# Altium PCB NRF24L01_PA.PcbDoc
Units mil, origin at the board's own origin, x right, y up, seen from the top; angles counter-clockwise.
Board outline 865.03 x 605.03 mil, 4 copper layers (Top Layer, Internal Plane 1, Signal Layer 1, Bottom Layer), stack 29.965 mil thick; 31 components, 23 nets, 111 pads, 55 vias.
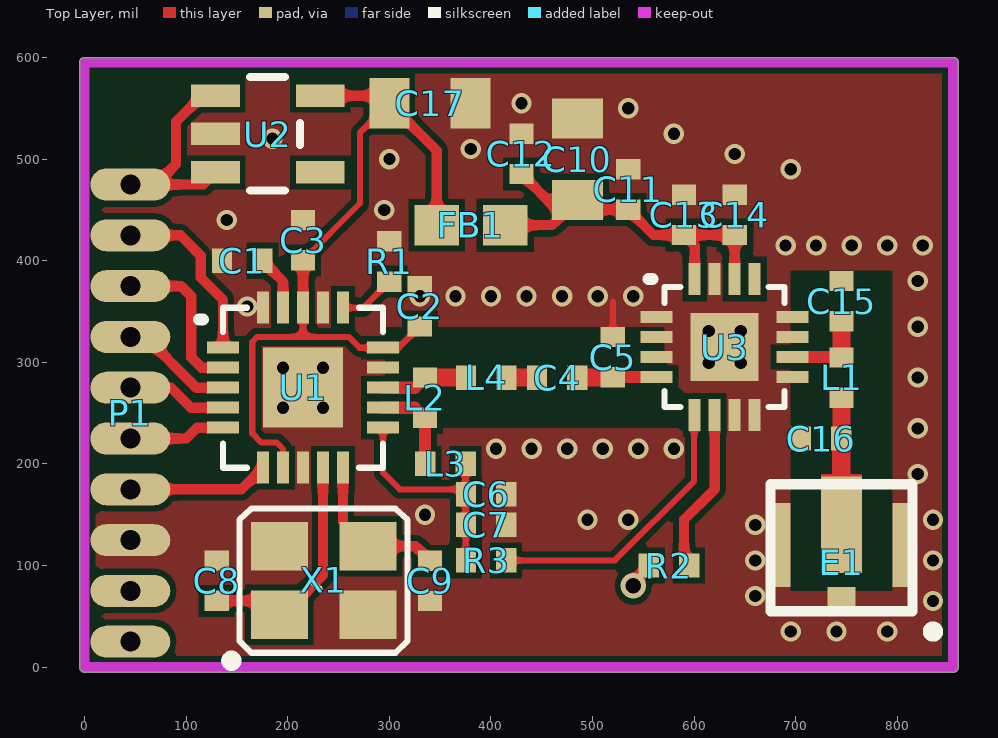
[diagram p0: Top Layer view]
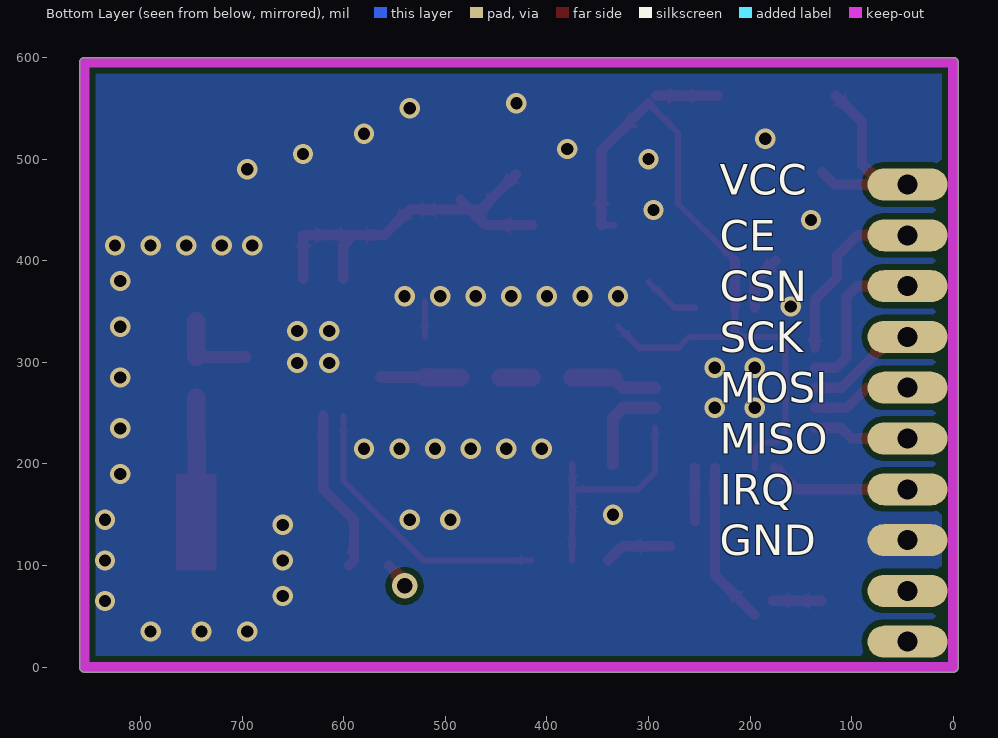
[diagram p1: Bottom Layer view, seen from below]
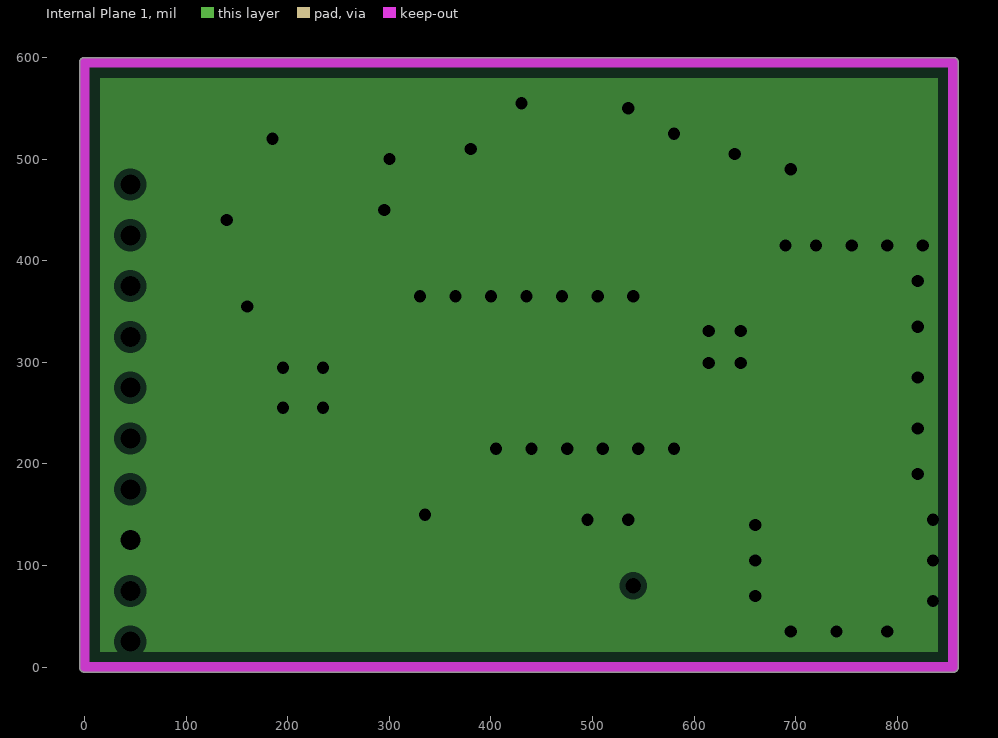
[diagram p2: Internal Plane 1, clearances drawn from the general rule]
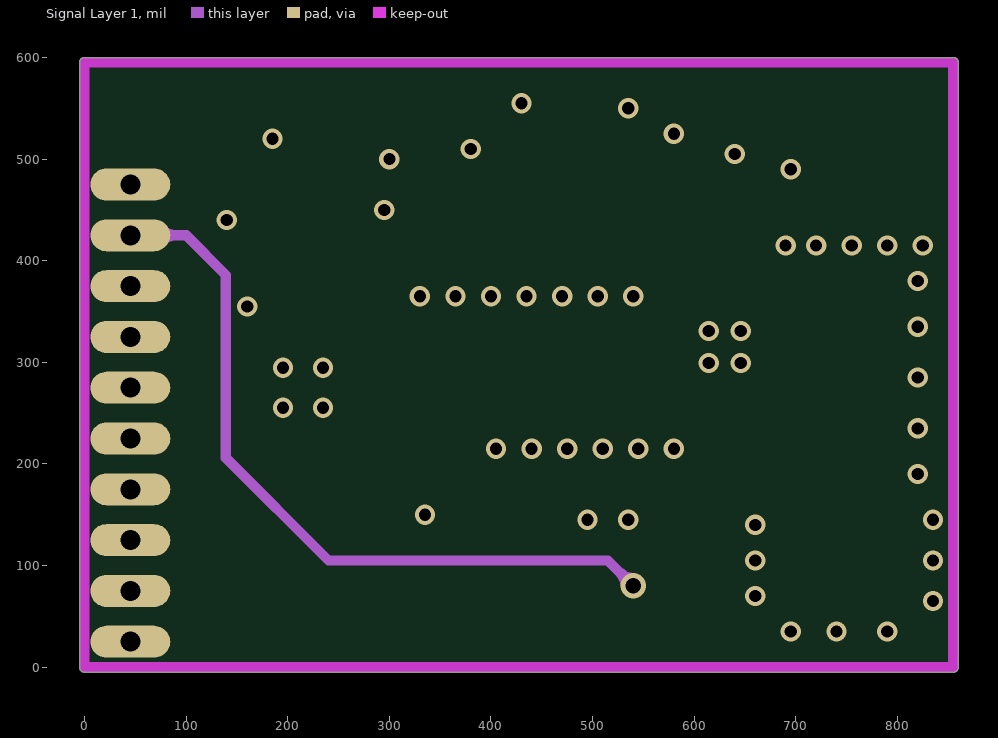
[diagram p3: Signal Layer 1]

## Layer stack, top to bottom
Top Layer: signal copper 1.4
Dielectric: prepreg 5, FR-4, Dk 4.2
Internal Plane 1: plane copper 0.7087, net GND
Dielectric: core 15.748, Dk 4.2
Signal Layer 1: signal copper 0.7087
Dielectric: prepreg 5, Dk 4.2
Bottom Layer: signal copper 1.4

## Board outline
-5.02,0 ccw(c0,0) 0,-5.02 855,-5.02 ccw(c855,0) 860.02,0 860.02,595 ccw(c855,595) 855,600.01 0,600.01 ccw(c0,595) -5.02,595

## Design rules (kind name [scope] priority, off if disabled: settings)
Clearance [All] p1: gap=6
ComponentClearance [All] p1: gap=10 collisioncheckmode=3 verticalgap=10
PlaneClearance [All] p1: clearance=6
PlaneConnect [All] p1: planeconnectstyle=NoConnect reliefexpansion=20 reliefentries=4 reliefconductorwidth=10 reliefairgap=10
PolygonConnect [All] p1: connectstyle=Direct reliefconductorwidth=10 reliefentries=4 polygonreliefangle="90 Angle"
RoomDefinition NRF24L01_PA [InComponentClass('NRF24L01_PA')] p1: confinementstyle=ConfineIn formatcopy=TRUE lockcomponents=FALSE outline 2765,-455 5630,-455 5630,-145 2765,-145
RoutingVias [All] p1: holewidth=28 width=50 viastyle="Through Hole" minholewidth=15 minwidth=20 maxholewidth=28 maxwidth=50
SolderMaskExpansion [All] p1 off: expansion=4
TestPointUsage FabricationTestPointUsage [All] p1: valid=0 allowmultiple=FALSE
Testpoint FabricationTestpoint [All] p1: side=3 testpointundercomponent=TRUE minsize=40 maxsize=100 preferedsize=60 minholesize=0 maxholesize=40 preferedholesize=32 testpointgrid=1 style=297 order=0123456789
Width [All] p1: maxlimit=20 minlimit=6 preferedwidth=10
16 further rules are at their usual default settings.

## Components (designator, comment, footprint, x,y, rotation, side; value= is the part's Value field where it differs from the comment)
C1 "Cap" 0402 155,400 r0 top
C2 "Cap" 0402 330,355 r90 top
C3 "Cap" 0402 215,420 r90 top
C4 "Cap" 0402 465,285 r0 top
C5 "Cap" 0402 520,305 r90 top
C6 "Cap" 0402 395,170 r0 top
C7 "Cap" 0402 395,140 r0 top
C8 "Cap" 0402 130,85 r90 top
C9 "Cap" 0402 340,85 r270 top
C10 "Cap" 0805 485,500 r90 top
C11 "Cap" 0402 535,470 r90 top
C12 "Cap" 0402 430,505 r90 top
C13 "Cap" 0402 590,445 r90 top
C14 "Cap" 0402 640,445 r90 top
C15 "Cap" 0402 745,360 r90 top
C16 "Cap" 0402 725,225 r180 top
C17 "Cap" 0805 340,555 r0 top (schematic designator C8)
E1 "Antenna" IPEX 745,120 r180 top
FB1 "Res2" 0603 380,435 r0 top
L1 "Inductor" 0402 745,285 r270 top
L2 "Inductor" 0402 335,265 r90 top
L3 "Inductor" 0402 355,200 r0 top
L4 "Inductor" 0402 395,285 r0 top (schematic designator L1)
P1 "RFInf" RFInf 45,475 r0 top
R1 "Res2" 0402 300,399.37 r270 top
R2 "Res2" 0402 575,100 r0 top
R3 "Res2" 0402 395,105 r0 top
U1 "NRF24L01" NRF24L01 215,275 r0 top
U2 "LP5907" SOT23-5 180,525 r270 top
U3 "RFX2401C" RFX2401C 630,315 r0 top
X1 "16Mhz" OSCILLATOR-3.2X2.5 235,85 r0 top

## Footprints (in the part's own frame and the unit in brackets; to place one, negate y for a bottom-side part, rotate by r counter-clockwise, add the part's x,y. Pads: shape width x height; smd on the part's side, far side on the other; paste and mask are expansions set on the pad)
0402 [mil] "0402-RES"
  rect 20x24 smd: 1(-19.69,0) 2(20,0)
0603 [mil] "0603-RES"
  rect 44x40 smd: 1(-33.46,0) 2(34,0)
0805 [mil]
  rect 39.37x50 smd: 1(-40,0) 2(40,0)
  body extent -50,-30 50,30, height 31
IPEX [mil]
  rect 40x95 smd: 1(0,-20)
  rect 19.68x82.68 smd: 2(-60,0) 2(60,0)
  rect 27.56x27.56 smd: 2(0,55)
  Top Layer region: -20,-70 20,-70 20,25 -20,25
  silkscreen extent -95,-60 70,90
NRF24L01 [mm]
  rect 2x2 smd: 0(0,0)
  rect 0.8x0.3 smd: 1(-2,1) 2(-2,0.5) 3(-2,0) 4(-2,-0.5) 5(-2,-1) 11(2,-1) 12(2,-0.5) 13(2,0) 14(2,0.5) 15(2,1)
  rect 0.3x0.8 smd: 6(-1,-2) 7(-0.5,-2) 8(0,-2) 9(0.5,-2) 10(1,-2) 16(1,2) 17(0.5,2) 18(0,2) 19(-0.5,2) 20(-1,2)
  silkscreen extent -2.6,-2 2,2
OSCILLATOR-3.2X2.5 [mil] "OSCILLATOR-3.2X2.5"
  rect 56x48 smd: 1(-43.31,-33.46) 2(44,-33.46) 3(44,34) 4(-43.31,34)
  silkscreen extent -95,-83 83,71
RFInf [mm]
  oval 2x0.8 hole 0.5: 1(0,0) 2(0,-1.27) 3(0,-2.54) 4(0,-3.81) 5(0,-5.08) 6(0,-6.35) 7(0,-7.62) 8(0,-8.89) 9(0,-10.16) 10(0,-11.43)
RFX2401C [mm]
  rect 1.7x1.7 smd: 0(0,0)
  rect 0.8x0.3 smd: 1(-1.7,0.75) 2(-1.7,0.25) 3(-1.7,-0.25) 4(-1.7,-0.75) 9(1.7,-0.75) 10(1.7,-0.25) 11(1.7,0.25) 12(1.7,0.75)
  rect 0.3x0.8 smd: 5(-0.75,-1.7) 6(-0.25,-1.7) 7(0.25,-1.7) 8(0.75,-1.7) 13(0.75,1.7) 14(0.25,1.7) 15(-0.25,1.7) 16(-0.75,1.7)
  silkscreen extent -1.9,-1.5 1.5,1.7
SOT23-5 [mil] "SOT23-5"
  rect 22x48 smd: 1(-37.4,-51.19) 2(0,-51.19) 3(38,-51.19) 4(38,52) 5(-37.4,52)
  silkscreen extent -56,-17 56,32

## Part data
C1 C2 C3 C4 C5 C6 C7 C8 C9 C10 C11 C12 C13 C14 C15 C16 C17: "Capacitor"
E1: "Generic Antenna"
FB1 R1 R2 R3: "Resistor"
X1: library part OSCILLATOR-3.2X2.5, "Crystal Oscillator in 3.2x2.5 SMD"

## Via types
v1: diameter 20, hole 12, Top Layer to Bottom Layer, tented both sides, 54 vias
v2: diameter 25, hole 15, Top Layer to Bottom Layer, tented both sides, 1 vias

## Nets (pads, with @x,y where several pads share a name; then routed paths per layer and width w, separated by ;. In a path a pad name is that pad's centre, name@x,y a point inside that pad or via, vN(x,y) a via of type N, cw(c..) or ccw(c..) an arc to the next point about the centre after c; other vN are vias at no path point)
3.3NRF: C2.1 C3.1 C17.1 FB1.1 U1.7 U1.15 U1.18 U2.5 | length 813.2
  Top Layer w6: U1.7 195.31,214.68 188.99,221.01 173.99,221.01 165,230 165,320 170,325 210,325 ; U1.18 215,330 ; C3.1 271,456.32 271,526 C17.1 ; C2.1 309.06,314.37 U1.15 270.63,314.37 260,325 220,325 ; FB1.1@332.76,435 FB1.1 ; 210,325 220,325 ; 210,325 215,330 ; 215,330 220,325
  Top Layer w10: U1.18 C3.1 ; U2.5 C17.1@292.6,562.4 ; C17.1 346.54,508.46 FB1.1
3.3PA: C10.1 C11.1 C12.1 C13.1 C14.1 FB1.2 U3.14 U3.16 | length 407.2
  Top Layer w10: FB1.2 460,435 C10.1@475.31,450.32 ; C12.1 465,450.32 C10.1@475.31,450.32 ; C10.1 C10.1@475.31,450.32 ; U3.16 600.47,414.84 C13.1 ; U3.14 C14.1@639.84,425.16 ; C14.1 C13.1 ; C10.1@475.31,450.32 C11.1 560,425.32 C13.1
5V: P1.1 U2.1 U2.3 | length 195.1
  Top Layer w10: P1.1 P1.1@70,475 ; U2.1@115.66,562.4 90,536.74 90,495 P1.1@70,475 ; U2.3 116.81,475 P1.1@70,475
CE: P1.2 R2.1 U1.1 | length 947
  Top Layer w10: P1.2 94.31,425 114.31,405 114.31,383.44 136.26,361.5 U1.1 ; v2(540,80) 540,84.68 R2.1
  Signal Layer 1 w10: P1.2 100,425 139,386 139,206 240,105 515,105 v2(540,80)
CSN: P1.3 U1.2 | length 159.7
  Top Layer w10: P1.3 95,375 105,365 105,305 115.31,294.68 U1.2
GND: C1.1 C2.2 C3.2 C5.2 C6.2 C7.2 C8.2 C9.2 C10.2 C11.2 C12.2 C13.2 C14.2 C15.2 C16.2 C17.2 E1.2 P1.8 R1.1 U1.0 U1.8 U1.14 U1.17 U1.20 U2.2 U3.0 U3.1 U3.2 U3.3 U3.7 U3.8 U3.9 U3.11 U3.12 U3.15 X1.2 X1.4 | length 35
  Top Layer w6: C5.2 520,360
  other v1: 695,35 740,35 790,35 835,65 660,70 660,105 835,105 660,140 495,145 535,145 835,145 335,150 820,190 405,215 440,215 475,215 510,215 545,215 580,215 820,235 195.31,255.32 234.69,255.32 820,285 195.31,294.68 234.69,294.68 614.25,299.25 645.75,299.25 614.25,330.75 645.75,330.75 820,335 160,355 330,365 365,365 400,365 435,365 470,365 505,365 540,365 820,380 690,415 720,415 755,415 790,415 825,415 140,440 295,450 695,490 300,500 640,505 380,510 185,520 580,525 535,550 430,555
IRQ: P1.7 U1.6 | length 139.4
  Top Layer w10: P1.7 154.37,175 U1.6
MISO: P1.6 U1.5 | length 95.7
  Top Layer w10: P1.6 100,225 110.63,235.63 U1.5
MOSI: P1.5 U1.4 | length 99.4
  Top Layer w10: P1.5 85,275 104.69,255.32 U1.4
NetC1_2: C1.2 U1.19 | length 54.7
  Top Layer w10: C1.2 195.31,379.68 U1.19
NetC4_1: C4.1 L4.2 | length 30.3
  Top Layer w18: L4.2 C4.1
NetC4_2: C4.2 C5.1 U3.4 | length 78.3
  Top Layer w12: C5.1 520.16,285.47 U3.4
  Top Layer w18: C4.2 519.69,285 C5.1
NetC6_1: C6.1 C7.1 L3.2 R3.1 U1.11 | length 222.4
  Top Layer w6: U1.11 293.74,191.26 310,175 C6.1@370.31,175 ; C7.1@375,140.32 L3.2 ; R3.1 C7.1
NetC8_1: C8.1 U1.9 X1.1 | length 208.8
  Top Layer w10: C8.1 X1.1@177.91,65.32 ; X1.1@195.69,51.54 234.69,90.53 U1.9
NetC9_1: C9.1 U1.10 X1.3 | length 119.6
  Top Layer w10: 254.37,143.63 U1.10 ; X1.3 325.69,119 C9.1
NetC15_1: C15.1 L1.1 U3.10 | length 83.6
  Top Layer w12: U3.10 744.53,305.16 L1.1
  Top Layer w18: L1.1@744.53,305.16 745,305.63 C15.1
NetC16_1: C16.1 E1.1 L1.2 | length 125.3
  Top Layer w6: C16.1 C16.1@745,225.32
  Top Layer w18: C16.1 744.69,140.32 E1.1 ; C16.1@745,225.32 L1.2
NetL2_1: L2.1 L3.1 U1.12 | length 91.3
  Top Layer w6: L2.1 L2.1@335.31,245
  Top Layer w12: U1.12 325,255.32 L2.1 335,200.32 L3.1
NetL2_2: L2.2 L4.1 U1.13 | length 85.7
  Top Layer w12: U1.13 325,275 L2.2
  Top Layer w18: L2.2 L4.1
NetR1_2: R1.2 U1.16 | length 56.2
  Top Layer w6: U1.16 274.37,353.74 R1.2
NetR2_2: R2.2 U3.6 | length 162.6
  Top Layer w10: R2.2 590,105 590,145 620.16,175.16 U3.6
NetR3_2: R3.2 U3.5 | length 281.8
  Top Layer w6: R3.2 521.87,105 600,183.13 U3.5@600,247.6
SCK: P1.4 U1.3 | length 97
  Top Layer w10: P1.4@60,325 110,275 U1.3
pads on no net: P1.9 P1.10 U2.4 U3.13

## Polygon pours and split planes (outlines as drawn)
GND on Top Layer "Top Layer-No Net" (solid, remove dead copper, pour order 2): 0,595 855,595 855,0 0,0
GND on Bottom Layer "Top Layer-No Net" (solid, remove dead copper, pour order 4): 0,595 855,595 855,0 0,0
GND on Internal Plane 1 (split plane): 839.92,15.08 15.08,15.08 15.08,579.92 839.92,579.92

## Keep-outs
Keep-Out Layer:
  lines w10: 0,0 855,0 855,595 0,595 0,0

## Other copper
Top Layer:
  pour cut-out: 695,390 795,390 795,75 695,75
  pour cut-out: 295.28,335 570.87,335 570.87,289.58 625.44,235 295.28,235

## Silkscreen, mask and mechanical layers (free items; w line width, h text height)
Bottom Overlay:
  text "VCC" at 230,465 h30
  text "CE" at 230,410 h30
  text "CSN" at 230,360 h30
  text "SCK" at 230,310 h30
  text "MOSI" at 230,260 h30
  text "MISO" at 230,210 h30
  text "IRQ" at 230,160 h30
  text "GND" at 230,110 h30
